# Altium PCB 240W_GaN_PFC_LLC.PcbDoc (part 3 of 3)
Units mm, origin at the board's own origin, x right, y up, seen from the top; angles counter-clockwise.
Board outline 105 x 71.8 mm, 4 copper layers (Top Layer, Layer 1, Layer 2, Bottom Layer), stack 1.787 mm thick; 165 components, 88 nets, 549 pads, 326 vias.
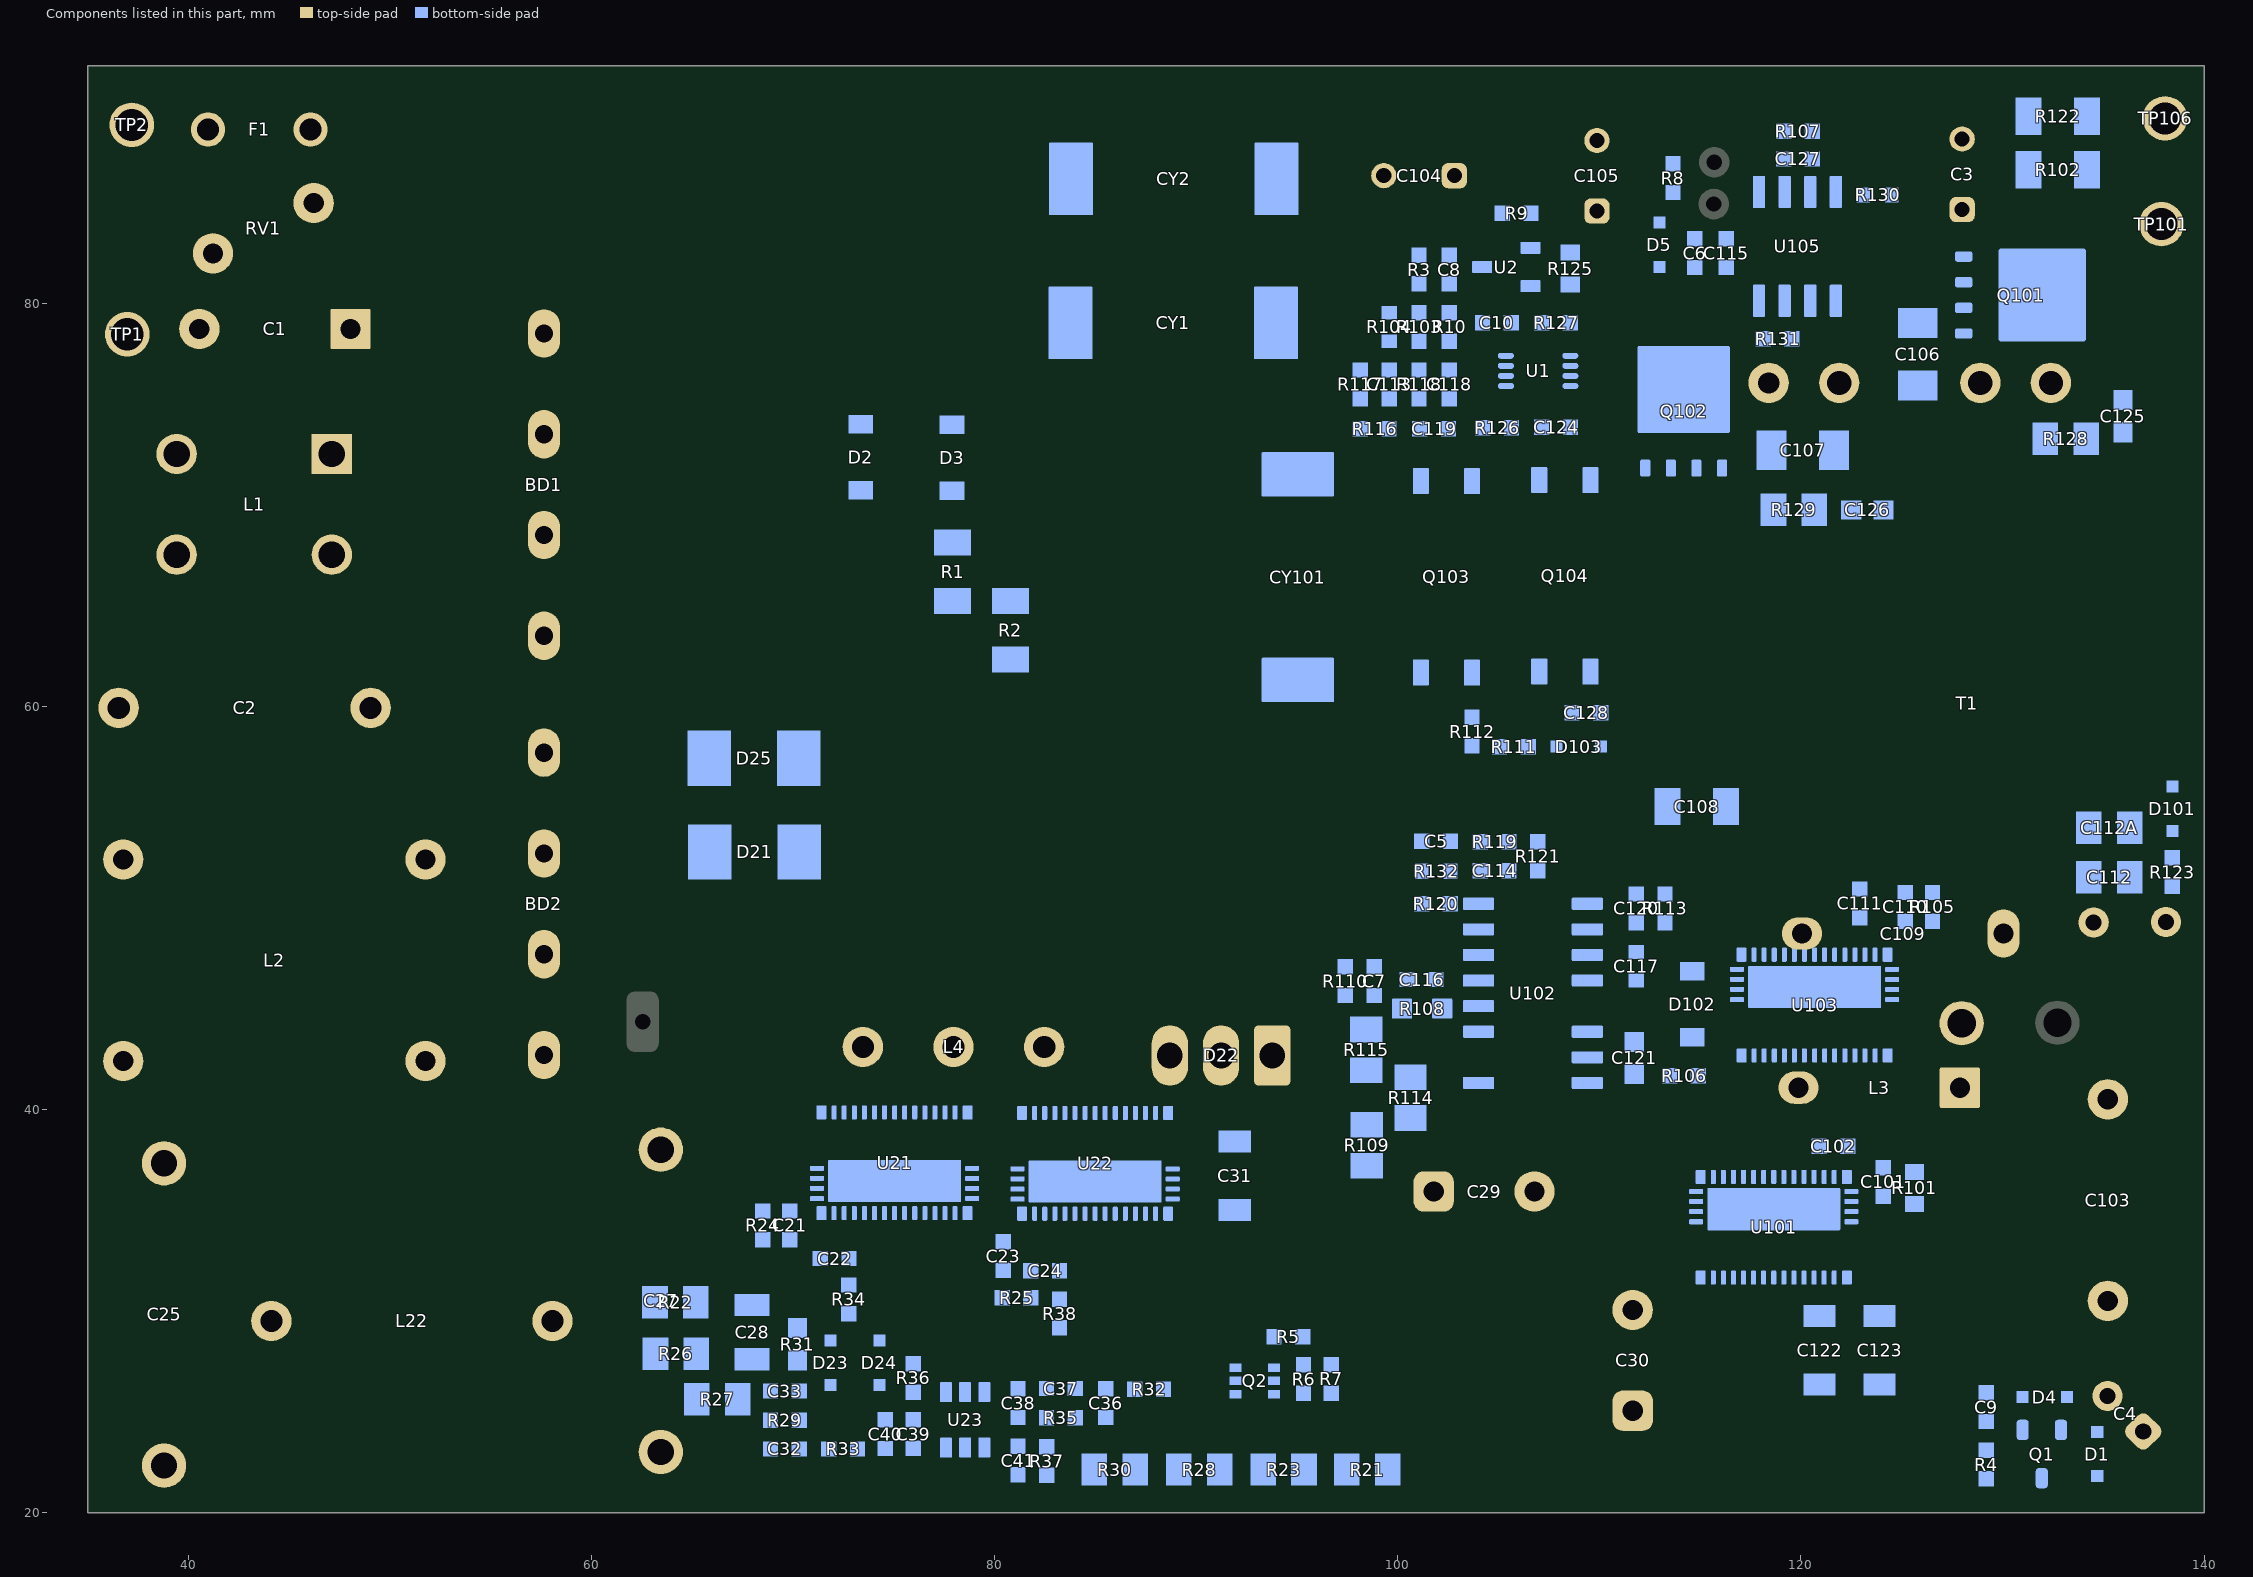
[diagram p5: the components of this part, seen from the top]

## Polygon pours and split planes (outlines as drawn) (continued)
PGND on Bottom Layer "BOTTOM_LAYER_PGND_P221" (solid, remove dead copper, pour order 221): 18 vertices, not listed, extent 115.425,45.105 124,51.95
NetC27_1 on Bottom Layer "BOTTOM_LAYER_NETC27_1_P197" (solid, remove dead copper, pour order 197): 19 vertices, not listed, extent 55.55,27.891 74.4,46
PGND on Bottom Layer "BOTTOM_LAYER_PGND_P196" (solid, remove dead copper, pour order 196): 18 vertices, not listed, extent 81.675,25.175 93.25,37.75
PGND on Bottom Layer "BOTTOM_LAYER_PGND_P195" (solid, remove dead copper, pour order 195): 18 vertices, not listed, extent 71.725,27.775 81.3,37.8
PGND on Bottom Layer "BOTTOM_LAYER_PGND_P182" (solid, remove dead copper, pour order 182): 35 vertices, not listed, extent 101.875,43.1 111.125,62.4
PGND on Bottom Layer "BOTTOM_LAYER_PGND_P181" (solid, remove dead copper, pour order 181): 122,53.175 126.1,53.175 126.9,52.375 126.9,50.4 124.75,50.4 124.6,50.55 124.175,50.55 123.825,50.2 123.575,50.2 123.2,50.575 122.55,50.575 122.55,52.25 122.575,52.275 122,52.85
SW on Bottom Layer "BOTTOM_LAYER_SW_P180" (solid, remove dead copper, pour order 180): 120.675,34.05 120.675,36.1 119.9,36.1 119.775,36.225 119.775,37.875 119.525,38.125 117.95,38.125 116.975,39.1 114.6,39.1 113.9,38.4 113.9,34.15 114.45,33.6 120.375,33.6 120.675,33.9
SW on Bottom Layer "BOTTOM_LAYER_SW_P179" (solid, remove dead copper, pour order 179): 123.7,43.6 117.7,43.6 117.575,43.475 117.575,41.9 119.325,40.15 121.95,40.15 123.15,41.35 123.15,42.05 123.525,42.425 123.8,42.7 123.8,43.5
PGND on Layer 2 "LAYER_2_PGND_P334" (solid, remove dead copper, pour order 334): 36 vertices, not listed, extent 105.475,22.925 126.897,51.406
NetC2_1 on Layer 2 "LAYER_2_NETC2_1_P302" (solid, remove dead copper, pour order 302): 17 vertices, not listed, extent 35.436,51.4 41.561,68.527
NetC2_2 on Layer 2 "LAYER_2_NETC2_2_P308" (solid, remove dead copper, pour order 308): 24 vertices, not listed, extent 35.625,41.35 50.025,68.75
NetC1_1 on Layer 2 "LAYER_2_NETC1_1_P349" (solid, remove dead copper, pour order 349): 18 vertices, not listed, extent 44.325,71.575 50.125,90.525
NetF1_2 on Layer 2 "LAYER_2_NETF1_2_P342" (solid, remove dead copper, pour order 342): 41.8,88.125 41.4,87.725 35.65,87.725 35.4,87.975 35.4,90.075 36,90.675 40.725,90.675 41.8,89.6
NetC1_2 on Layer 2 "LAYER_2_NETC1_2_P345" (solid, remove dead copper, pour order 345): 21 vertices, not listed, extent 35.401,70.629 42.175,83.65
NetL3_1 on Layer 2 "LAYER_2_NETL3_1_P340" (solid, remove dead copper, pour order 340): 126.45,40.45 126.95,39.95 128.975,39.95 129.275,40.25 129.275,44.849 128.724,45.4 127.383,45.4 126.45,44.467
NetC103_2 on Layer 2 "LAYER_2_NETC103_2_P338" (solid, remove dead copper, pour order 338): 130.992,49.925 131.473,49.443 131.473,48.75 136.651,43.572 136.651,39.374 135.951,38.674 133.076,38.674 130.9,40.85 130.9,44.8 129.225,46.475 129.225,49.45 129.7,49.925
PGND on Layer 2 "LAYER_2_PGND_P293" (solid, remove dead copper, pour order 293): 35 vertices, not listed, extent 96.975,43.075 137.1,62.4
390V_BUS on Layer 2 "LAYER_2_390V_BUS_P335" (solid, remove dead copper, pour order 335): 112.15,26.375 108.6,26.375 103.325,31.65 103.325,36.225 102.2,37.35 100.9,37.35 100.05,36.5 100.05,26.65 102.95,23.75 112.125,23.75 112.7,24.325 112.7,25.825
VFB on Layer 2 "LAYER_2_VFB_P331" (solid, remove dead copper, pour order 331): 139.313,84.813 138.73,85.395 127.645,85.395 127.25,85 127.25,82.934 128.984,81.2 138.8,81.2 139.313,81.712
RTN on Layer 2 "LAYER_2_RTN_P329" (solid, remove dead copper, pour order 329): 103.627,85.115 107.073,85.115 110.05,82.138 110.05,71.038 109.455,70.442 99.881,70.442 98.2,72.123 98.2,79.688
RTN on Layer 2 "LAYER_2_RTN_P328" (solid, remove dead copper, pour order 328): 29 vertices, not listed, extent 92.925,66.375 139.353,91.075
OCP on Layer 2 "LAYER_2_OCP_P326" (solid, remove dead copper, pour order 326): 138.8,91.075 134.051,91.075 133.525,90.549 133.525,86.129 133.559,86.129 133.962,85.725 139.025,85.725 139.325,86.025 139.325,90.55
VFB on Layer 2 "LAYER_2_VFB_P287" (solid, remove dead copper, pour order 287): 128.45,70.2 128.45,74.412 130.013,75.975 132.534,75.975 133.225,75.284 133.225,72.794 131.731,71.3 131.731,70.278 131.216,69.762 128.962,69.762
VFB on Layer 2 "LAYER_2_VFB_P283" (solid, remove dead copper, pour order 283): 128.225,70.55 128.225,72.15 131.375,75.3 136.55,75.3 137.45,74.4 137.45,70.425 136,68.975 129.7,68.975
BD+ on Layer 2 "LAYER_2_BD+_P272" (solid, remove dead copper, pour order 272): 63.821,87.075 67.04,87.075 75.79,78.325 84.025,78.325 85.575,76.775 85.575,67.308 91.002,61.881 91.043,61.881 91.043,50.22 89.273,48.45 74.449,48.45 71.062,51.837 69.456,51.837 69.094,51.475 63.846,51.475
NetBD1_2 on Layer 2 "LAYER_2_NETBD1_2_P269" (solid, remove dead copper, pour order 269): 59.25,74.175 59.25,68.175 58.1,67.025 54.6,67.025 53.25,68.375 53.25,73.65 54.6,75 58.425,75
BD+ on Layer 2 "LAYER_2_BD+_P227" (solid, remove dead copper, pour order 227): 19 vertices, not listed, extent 54.6,51.475 66.925,87.075
NetBD2_2 on Layer 2 "LAYER_2_NETBD2_2_P232" (solid, remove dead copper, pour order 232): 17 vertices, not listed, extent 50.6,41.375 59,54.075
BD+ on Layer 2 "LAYER_2_BD+_P260" (solid, remove dead copper, pour order 260): 27 vertices, not listed, extent 36.825,28.65 55.9,59.325
PGND on Layer 2 "LAYER_2_PGND_P253" (solid, remove dead copper, pour order 253): 26 vertices, not listed, extent 36.3,21.05 65.325,48.625
SW on Layer 2 "LAYER_2_SW_P214" (solid, remove dead copper, pour order 214): 120.875,42.775 120.125,43.525 115.682,43.525 114.932,44.275 108.65,44.275 108.025,43.65 108.025,40.537 108.462,40.1 112.025,40.1 113.9,38.225 113.9,34.175 114.45,33.625 120.31,33.625 120.875,34.19
PGND on Layer 2 "LAYER_2_PGND_P202" (solid, remove dead copper, pour order 202): 33 vertices, not listed, extent 71.725,25.175 93.2,38.732
NetC27_1 on Layer 2 "LAYER_2_NETC27_1_P199" (solid, remove dead copper, pour order 199): 17 vertices, not listed, extent 55.55,27.891 74.382,46
PGND on Layer 2 "LAYER_2_PGND_P191" (solid, remove dead copper, pour order 191): 50 vertices, not listed, extent 66.975,21 87.875,37.5
PGND on Layer 1 "LAYER_1_PGND_P216" (solid, remove dead copper, pour order 216): 112.025,32.05 131.075,32.05 132.9,30.225 132.9,23.375 131.95,22.425 116.857,22.425 115.682,23.6 115.682,26.768 115.36,27.09 112.025,27.09
PGND on Layer 1 "LAYER_1_PGND_P194" (solid, remove dead copper, pour order 194): 88.3,38.925 69.575,38.925 62.125,31.475 62.125,22.025 63.05,21.1 107.5,21.1 113.35,26.95 113.35,31.825 111.896,33.279 111.896,36.97 110.991,37.875 106.375,37.875 96.325,37.875 95.275,38.925
VFB on Layer 1 "LAYER_1_VFB_P358" (solid, remove dead copper, pour order 358): 32 vertices, not listed, extent 92.925,66.386 139.353,91.1
NetC2_2 on Layer 1 "LAYER_1_NETC2_2_P356" (solid, remove dead copper, pour order 356): 24 vertices, not listed, extent 35.625,41.35 50.025,68.75
NetC2_1 on Layer 1 "LAYER_1_NETC2_1_P355" (solid, remove dead copper, pour order 355): 17 vertices, not listed, extent 35.436,51.4 41.561,68.527
NetC1_1 on Layer 1 "LAYER_1_NETC1_1_P350" (solid, remove dead copper, pour order 350): 19 vertices, not listed, extent 44.325,70.625 50.125,90.525
NetF1_2 on Layer 1 "LAYER_1_NETF1_2_P346" (solid, remove dead copper, pour order 346): 41.8,88.125 41.4,87.725 35.65,87.725 35.4,87.975 35.4,90.075 36,90.675 40.725,90.675 41.8,89.6
NetC1_2 on Layer 1 "LAYER_1_NETC1_2_P347" (solid, remove dead copper, pour order 347): 21 vertices, not listed, extent 35.401,70.629 42.175,83.65
NetC103_2 on Layer 1 "LAYER_1_NETC103_2_P341" (solid, remove dead copper, pour order 341): 130.992,49.925 131.473,49.443 131.473,48.75 136.651,43.572 136.651,39.374 135.951,38.674 133.076,38.674 130.9,40.85 130.9,44.8 129.225,46.475 129.225,49.45 129.7,49.925
NetL3_1 on Layer 1 "LAYER_1_NETL3_1_P339" (solid, remove dead copper, pour order 339): 126.45,40.45 126.95,39.95 128.975,39.95 129.275,40.25 129.275,44.849 128.724,45.4 127.383,45.4 126.45,44.467
OCP on Layer 1 "LAYER_1_OCP_P325" (solid, remove dead copper, pour order 325): 138.8,91.075 134.051,91.075 133.525,90.549 133.525,86.129 133.559,86.129 133.962,85.725 139.025,85.725 139.325,86.025 139.325,90.55
VCCP on Layer 1 "LAYER_1_VCCP_P219" (solid, remove dead copper, pour order 219): 31 vertices, not listed, extent 99.775,42.55 139.566,62.339
PGND on Layer 1 "LAYER_1_PGND_P271" (solid, remove dead copper, pour order 271): 50 vertices, not listed, extent 49.15,28.653 91.966,85.525
BD+ on Layer 1 "LAYER_1_BD+_P255" (solid, remove dead copper, pour order 255): 43.95,39.2 46.65,36.5 46.65,29.775 45.15,28.275 38.875,28.275 35.825,31.325 35.825,37.975 37.05,39.2
NetBD1_2 on Layer 1 "LAYER_1_NETBD1_2_P265" (solid, remove dead copper, pour order 265): 20 vertices, not listed, extent 50.125,51.4 59.2,74.925
NetBD2_2 on Layer 1 "LAYER_1_NETBD2_2_P263" (solid, remove dead copper, pour order 263): 17 vertices, not listed, extent 50.6,41.375 59,54.075
PGND on Layer 1 "LAYER_1_PGND_P254" (solid, remove dead copper, pour order 254): 36.75,24.275 36.75,22.325 38.075,21 64.1,21 65.325,22.225 65.325,27.2 62.658,27.2 60.908,25.45 37.925,25.45
PGND on Layer 1 "LAYER_1_PGND_P222" (solid, remove dead copper, pour order 222): 121.1,46.025 121.1,45.15 122.405,43.845 122.405,32.605 121.675,31.875 121.675,30.275 122.225,29.725 127.675,29.725 127.7,29.75 127.65,29.8 127.65,31.425 124.95,34.125 124.95,44.925 123.825,46.05
PGND on Layer 1 "LAYER_1_PGND_P217" (solid, remove dead copper, pour order 217): 116.4,51.925 115.325,50.85 115.325,46.125 116.345,45.105 123.78,45.105 124,45.325 124,47.455 123.83,47.625 122.025,47.625 121.825,47.825 121.825,48.075 121.25,48.65 121.25,51.55 120.875,51.925
SW on Layer 1 "LAYER_1_SW_P213" (solid, remove dead copper, pour order 213): 120.875,42.775 120.125,43.525 115.682,43.525 114.932,44.275 110.494,44.275 109.525,43.306 109.525,40.932 110.357,40.1 112.025,40.1 113.9,38.225 113.9,34.175 114.45,33.625 120.31,33.625 120.875,34.19
NetC27_1 on Layer 1 "LAYER_1_NETC27_1_P193" (solid, remove dead copper, pour order 193): 17 vertices, not listed, extent 55.55,27.891 74.353,46
VFB on Top Layer "TOP_LAYER_VFB_P357" (solid, remove dead copper, pour order 357): 32 vertices, not listed, extent 92.925,66.386 139.353,91.1
NetC2_1 on Top Layer "TOP_LAYER_NETC2_1_P351" (solid, remove dead copper, pour order 351): 17 vertices, not listed, extent 35.436,51.4 41.561,68.527
NetC2_2 on Top Layer "TOP_LAYER_NETC2_2_P352" (solid, remove dead copper, pour order 352): 24 vertices, not listed, extent 35.625,41.35 50.025,68.75
NetC1_1 on Top Layer "TOP_LAYER_NETC1_1_P250" (solid, remove dead copper, pour order 250): 19 vertices, not listed, extent 44.325,70.625 50.125,90.525
NetC1_2 on Top Layer "TOP_LAYER_NETC1_2_P311" (solid, remove dead copper, pour order 311): 21 vertices, not listed, extent 35.401,70.629 42.175,83.65
NetF1_2 on Top Layer "TOP_LAYER_NETF1_2_P243" (solid, remove dead copper, pour order 243): 41.8,88.125 41.4,87.725 35.65,87.725 35.4,87.975 35.4,90.075 36,90.675 40.725,90.675 41.8,89.6
NetC103_2 on Top Layer "TOP_LAYER_NETC103_2_P336" (solid, remove dead copper, pour order 336): 130.992,49.925 131.473,49.443 131.473,48.75 136.651,43.572 136.651,39.374 135.951,38.674 133.076,38.674 130.9,40.85 130.9,44.8 129.225,46.475 129.225,49.45 129.7,49.925
NetL3_1 on Top Layer "TOP_LAYER_NETL3_1_P282" (solid, remove dead copper, pour order 282): 126.45,40.45 126.95,39.95 128.975,39.95 129.275,40.25 129.275,44.849 128.724,45.4 127.383,45.4 126.45,44.467
OCP on Top Layer "TOP_LAYER_OCP_P327" (solid, remove dead copper, pour order 327): 138.8,91.075 134.051,91.075 133.525,90.549 133.525,86.129 133.559,86.129 133.962,85.725 139.025,85.725 139.325,86.025 139.325,90.55
BD+ on Top Layer "TOP_LAYER_BD+_P268" (solid, remove dead copper, pour order 268): 43.963,39.212 46.663,36.512 46.663,29.787 45.163,28.287 38.888,28.287 35.838,31.338 35.838,37.987 37.063,39.212
NetBD2_2 on Top Layer "TOP_LAYER_NETBD2_2_P262" (solid, remove dead copper, pour order 262): 17 vertices, not listed, extent 50.6,41.375 59,54.075
PGND on Top Layer "TOP_LAYER_PGND_P256" (solid, remove dead copper, pour order 256): 36.75,24.275 36.75,22.325 38.075,21 64.1,21 65.325,22.225 65.325,27.2 62.658,27.2 60.908,25.45 37.925,25.45
NetC1_1 on Top Layer "TOP_LAYER_NETC1_1_P241" (solid, remove dead copper, pour order 241): 19 vertices, not listed, extent 44.15,70.625 50.125,90.525
PGND on Top Layer "TOP_LAYER_PGND_P236" (solid, remove dead copper, pour order 236): 30 vertices, not listed, extent 62.325,42.324 105.95,90.55
PGND on Top Layer "TOP_LAYER_PGND_P230" (solid, remove dead copper, pour order 230): 19 vertices, not listed, extent 56.7,41.25 64.325,65.55
NetBD1_2 on Top Layer "TOP_LAYER_NETBD1_2_P228" (solid, remove dead copper, pour order 228): 17 vertices, not listed, extent 50.125,51.4 59.2,74.925
390V_BUS on Top Layer "TOP_LAYER_390V_BUS_P226" (solid, remove dead copper, pour order 226): 22 vertices, not listed, extent 90.35,23.45 112.975,44.455
PGND on Top Layer "TOP_LAYER_PGND_P223" (solid, remove dead copper, pour order 223): 35 vertices, not listed, extent 93.65,29.025 128.025,62.525
PGND on Top Layer "TOP_LAYER_PGND_P218" (solid, remove dead copper, pour order 218): 116.65,51.9 115.775,51.025 115.775,48.7 115.325,48.25 115.325,46.125 116.345,45.105 123.78,45.105 124,45.325 124,47.175 121.675,49.5 121.675,51.35 121.125,51.9
SW on Top Layer "TOP_LAYER_SW_P215" (solid, remove dead copper, pour order 215): 120.95,42.7 120.125,43.525 115.682,43.525 114.932,44.275 110.494,44.275 109.525,43.306 109.525,40.932 110.357,40.1 112.025,40.1 113.9,38.225 113.9,34.175 114.45,33.625 120.31,33.625 120.95,34.265
390V_BUS on Top Layer "TOP_LAYER_390V_BUS_P212" (solid, remove dead copper, pour order 212): 137.3,30.9 137.3,28.7 136.45,27.85 128.5,27.85 127.6,28.75 118.5,28.75 116.95,27.2 116.95,24.225 116.175,23.45 108.675,23.45 108.675,27.125 112.625,27.125 117.6,32.1 136.1,32.1
PGND on Top Layer "TOP_LAYER_PGND_P211" (solid, remove dead copper, pour order 211): 118.575,26.6 118.575,23.55 119.625,22.5 126.825,22.5 127.425,23.1 127.425,26.375 126.625,27.175 119.15,27.175
LMG_VCC on Top Layer "TOP_LAYER_LMG_VCC_P201" (solid, remove dead copper, pour order 201): 21 vertices, not listed, extent 70.375,21.175 83.875,34.825
PGND on Top Layer "TOP_LAYER_PGND_P200" (solid, remove dead copper, pour order 200): 29 vertices, not listed, extent 62.15,21 93.25,38.925
NetC27_1 on Top Layer "TOP_LAYER_NETC27_1_P198" (solid, remove dead copper, pour order 198): 17 vertices, not listed, extent 55.55,27.891 74.4,46

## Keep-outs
Keep-Out Layer:
  the board outline again, w0.2
  text ".Layer_Name" at 14.656,-21.806 h1.52

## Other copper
Top Layer:
  pour cut-out: 123.38,52.081 ccw(c123.88,52.081) 123.88,51.581 ccw(c123.88,52.081) 124.38,52.081 ccw(c123.88,52.081) 123.88,52.581 ccw(c123.88,52.081)
  pour cut-out: 95.2,28.405 ccw(c96.7,28.405) 96.7,26.905 ccw(c96.7,28.405) 98.2,28.405 ccw(c96.7,28.405) 96.7,29.905 ccw(c96.7,28.405)
  pour cut-out: 93.772,29.75 ccw(c95.272,29.75) 95.272,28.25 ccw(c95.272,29.75) 96.772,29.75 ccw(c95.272,29.75) 95.272,31.25 ccw(c95.272,29.75)
  pour cut-out: 105.429,72.607 ccw(c105.929,72.607) 105.929,72.107 ccw(c105.929,72.607) 106.429,72.607 ccw(c105.929,72.607) 105.929,73.107 ccw(c105.929,72.607)
  pour cut-out: 77.9,78.784 cw(c77.9,80.484) 76.2,80.484 cw(c77.9,80.484) 77.9,82.184 cw(c77.9,80.484) 79.6,80.484 cw(c77.9,80.484)
  pour cut-out: 75.643,85.775 cw(c75.643,87.475) 73.943,87.475 cw(c75.643,87.475) 75.643,89.175 cw(c75.643,87.475) 77.343,87.475 cw(c75.643,87.475)
  pour cut-out: 82.475,60.748 cw(c82.475,62.348) 80.875,62.348 cw(c82.475,62.348) 82.475,63.948 cw(c82.475,62.348) 84.075,62.348 cw(c82.475,62.348)
  pour cut-out: 70.325,48.335 cw(c70.325,49.935) 68.725,49.935 cw(c70.325,49.935) 70.325,51.535 cw(c70.325,49.935) 71.925,49.935 cw(c70.325,49.935)
  pour cut-out: 112.189,48.225 ccw(c112.789,48.225) 112.789,47.625 ccw(c112.789,48.225) 113.389,48.225 ccw(c112.789,48.225) 112.789,48.825 ccw(c112.789,48.225)
  pour cut-out: 99.18,47.454 ccw(c99.78,47.454) 99.78,46.854 ccw(c99.78,47.454) 100.38,47.454 ccw(c99.78,47.454) 99.78,48.054 ccw(c99.78,47.454)
  text ".Layer_Name" at 14.656,-21.806 h1.52
Layer 1:
  pour cut-out: 81.294,29.61 ccw(c81.794,29.61) 81.794,29.11 ccw(c81.794,29.61) 82.294,29.61 ccw(c81.794,29.61) 81.794,30.11 ccw(c81.794,29.61)
  pour cut-out: 105.444,72.592 ccw(c105.944,72.592) 105.944,72.092 ccw(c105.944,72.592) 106.444,72.592 ccw(c105.944,72.592) 105.944,73.092 ccw(c105.944,72.592)
  pour cut-out: 77.9,78.784 cw(c77.9,80.484) 76.2,80.484 cw(c77.9,80.484) 77.9,82.184 cw(c77.9,80.484) 79.6,80.484 cw(c77.9,80.484)
  pour cut-out: 99.275,35.873 ccw(c101.775,35.873) 101.775,33.373 ccw(c101.775,35.873) 104.275,35.873 ccw(c101.775,35.873) 101.775,38.373 ccw(c101.775,35.873)
  pour cut-out: 109.15,25.075 ccw(c111.65,25.075) 111.65,22.575 ccw(c111.65,25.075) 114.15,25.075 ccw(c111.65,25.075) 111.65,27.575 ccw(c111.65,25.075)
  pour cut-out: 76.3,26.05 ccw(c76.9,26.05) 76.9,25.45 ccw(c76.9,26.05) 77.5,26.05 ccw(c76.9,26.05) 76.9,26.65 ccw(c76.9,26.05)
  pour cut-out: 70.7,31.55 ccw(c71.3,31.55) 71.3,30.95 ccw(c71.3,31.55) 71.9,31.55 ccw(c71.3,31.55) 71.3,32.15 ccw(c71.3,31.55)
Layer 2:
  pour cut-out: 132.625,54.165 ccw(c133.125,54.165) 133.125,53.665 ccw(c133.125,54.165) 133.625,54.165 ccw(c133.125,54.165) 133.125,54.665 ccw(c133.125,54.165)
Bottom Layer:
  text ".Layer_Name" at 14.656,-21.806 h1.52

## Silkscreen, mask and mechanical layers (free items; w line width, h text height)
Top Overlay:
  rectangle: 60.05,39.775 62.05,90.775
  rectangle: 34.975,90.8 140,91.8
  rectangle: 35,20 140,21
  text ".Layer_Name" at 14.656,-21.806 h1.52
Bottom Overlay:
  rectangle: 34.975,90.8 140,91.8
  rectangle: 34.975,20 140,21
  text "'.PRJ_Number'.PCB_Rev" at 88.25,56.7 h2.75
  text ".Layer_Name" at 14.656,-21.806 h1.52
Top Paste:
  text ".Layer_Name" at 14.656,-21.806 h1.52
Bottom Paste:
  text ".Layer_Name" at 14.656,-21.806 h1.52
Top Solder:
  text ".Layer_Name" at 14.656,-21.806 h1.52
  text ".Layer_Name" at 14.656,-21.806 h1.52
Bottom Solder:
  text ".Layer_Name" at 14.656,-21.806 h1.52
Drill Guide:
  text ".Layer_Name" at 14.656,-21.806 h1.52
M1 Board Outline:
  the board outline again, w0.2
  text ".Layer_Name" at 14.656,-21.806 h1.52
M2 Board Dimensions:
  rectangle: 0,-6.985 3.175,-3.81
  rectangle: 3.175,-10.16 12.7,-6.985
  lines w0.178: 0,-6.985 25.4,-6.985 ; 3.175,-10.16 3.175,-3.81 ; 6.35,-10.16 6.35,-3.81 ; 12.7,-10.16 12.7,-3.81 ; 19.05,-10.16 19.05,-3.81 ; 0,-10.16 25.4,-10.16 25.4,-3.81 0,-3.81 0,-10.16
  text ".Layer_Name" at 14.656,-21.806 h1.52
M3 3D STEP Top:
  text ".Layer_Name" at 14.656,-21.806 h1.52
M4 3D STEP Bottom:
  text ".Layer_Name" at 14.656,-21.806 h1.52
M5 Assembly Top:
  lines w0.254: -7.417,-23.626 160.223,-23.626 ; -7.417,-18.462 160.274,-18.462 ; -7.417,-13.297 -7.417,-28.791 94.31,-28.791 160.274,-28.791 160.274,-13.297 -7.404,-13.297 -7.404,-28.791 32.614,-28.791 ; 55.194,-28.791 55.194,-13.297 ; 87.376,-18.462 87.376,-13.297 ; 108.712,-18.462 108.712,-13.297 ; 124.511,-28.956 124.511,-23.804
  text "COMPONENTS MARKED 'DNP' SHOULD NOT BE POPULATED." at 29.299,-8.09 h1.52
  text "ASSEMBLY VARIANT:" at 29.286,-11.024 h1.52
  text ".VariantName" at 55.601,-11.024 h1.52
  text "PCB VIEWED FROM TOP SIDE" at -5.804,-16.654 h1.52
  text "BOARD #:" at 57.099,-16.654 h1.52
  text ".PRJ_Number" at 70.955,-16.654 h1.52
  text "REV:" at 92.405,-16.654 h1.52
  text ".PCB_Rev" at 99.809,-16.654 h1.52
  text "SVN REV:" at 113.69,-16.654 h1.52
  text ".VersionControl_RevNumber" at 126.543,-16.654 h1.52
  text "TID #:" at 57.099,-21.819 h1.52
  text ".TID" at 70.955,-21.819 h1.52
  text "PLOT NAME =" at -5.804,-27.034 h1.52
  text ".plot_File_Name" at 14.656,-27.034 h1.52
  text "GENERATED    :" at 57.15,-27.034 h1.52
  text ".Print_Date" at 79.235,-27.034 h1.52
  text ".Print_Time" at 97.752,-27.034 h1.52
  text "TEXAS INSTRUMENTS" at 129.87,-27.034 h1.52
M6 Assembly Bottom:
  lines w0.254: -7.429,-18.474 160.261,-18.474 ; -7.379,-23.639 160.261,-23.639 ; 28.334,-28.969 28.334,-23.817 ; 44.133,-18.474 44.133,-13.31 ; 65.468,-18.474 65.468,-13.31 ; 97.65,-28.804 97.65,-13.31 ; 120.231,-28.804 160.249,-28.804 160.249,-13.31 -7.429,-13.31 -7.429,-28.804 58.534,-28.804 160.261,-28.804 160.261,-13.31
  text "COMPONENTS MARKED 'DNP' SHOULD NOT BE POPULATED." at 154.991,-8.077 h1.52
  text ".VariantName" at 128.473,-11.024 h1.52
  text "ASSEMBLY VARIANT:" at 154.864,-11.024 h1.52
  text ".VersionControl_RevNumber" at 26.302,-16.667 h1.52
  text "SVN REV:" at 39.154,-16.667 h1.52
  text ".PCB_Rev" at 53.035,-16.667 h1.52
  text "REV:" at 60.439,-16.667 h1.52
  text ".PRJ_Number" at 81.89,-16.667 h1.52
  text "BOARD #:" at 95.745,-16.667 h1.52
  text "PCB VIEWED FROM BOTTOM SIDE" at 158.648,-16.667 h1.52
  text ".TID" at 81.89,-21.831 h1.52
  text "TID #:" at 95.745,-21.831 h1.52
  text "TEXAS INSTRUMENTS" at 22.974,-27.047 h1.52
  text ".Print_Time" at 55.093,-27.047 h1.52
  text ".Print_Date" at 73.609,-27.047 h1.52
  text "GENERATED    :" at 95.694,-27.047 h1.52
  text ".plot_File_Name" at 138.189,-27.047 h1.52
  text "PLOT NAME =" at 158.648,-27.047 h1.52
M9 Title Sheet:
  drawing of 57 lines, arcs and shapes, not listed
  text "1" at 18.792,204.127 h1.78
  text "2" at 82.182,204.127 h1.78
  text "3" at 145.411,204.127 h1.78
  text "4" at 209.08,204.127 h1.78
  text "5" at 272.555,204.127 h1.78
  text "6" at 336.182,204.127 h1.78
  text "A" at -10.579,175.095 h1.78
  text "A" at 365.341,175.095 h1.78
  text "B" at -10.579,114.643 h1.78
  text "B" at 365.341,114.643 h1.78
  text "C" at -10.579,54.318 h1.78
  text "C" at 365.341,54.318 h1.78
  text "PROJECT TITLE:" at 288.125,7.048 h1.14
  text ".PRJ_Title" at 289.395,3.662 h1.78
  text "DESIGNED FOR:" at 288.125,-0.597 h1.14
  text ".PRJ_Customer" at 289.395,-4.153 h1.78
  text "D" at -10.579,-5.88 h1.78
  text "D" at 365.341,-5.88 h1.78
  text "FILE NAME:" at 288.125,-8.217 h1.14
  text ".PCB_File_Name_No_Path" at 289.395,-11.265 h1.78
  text "Texas Instruments (TI) and/or its licensors do not warrant the accuracy or completeness of this specification" at 161.9,-15.376 h1.14
  text "ENGINEER:" at 288.125,-15.583 h1.14
  text "LAYOUT BY:" at 326.352,-15.583 h1.14
  text "or any information contained therein. TI and/or its licensors do not warrant that this design will meet" at 160.757,-18.237 h1.14
  text ".PRJ_Engineer" at 289.395,-19.52 h1.78
  text ".PCB_Layout" at 327.635,-19.52 h1.78
  text "the specifications, will be suitable for your application or fit for any particular purpose, or will operate in" at 160.757,-21.099 h1.14
  text ".Layer_Name" at 14.656,-21.806 h1.52
  text "ALTIUM DESIGNER VERSION:" at 326.352,-23.457 h1.14
  text "an implementation. TI and/or its licensors do not warrant that the design is production worthy. You should" at 160.757,-23.961 h1.14
  text "completely validate and test your design implementation to confirm the system functionality for your application." at 161.9,-26.822 h1.14
  text ".print_Scale" at 289.395,-26.843 h1.78
  text ".Application_BuildNumber" at 327.635,-26.843 h1.78
  text "1" at 18.792,-32.093 h1.78
  text "2" at 82.182,-32.093 h1.78
  text "3" at 145.411,-32.093 h1.78
  text "4" at 209.08,-32.093 h1.78
  text "5" at 272.555,-32.093 h1.78
  text "6" at 336.182,-32.093 h1.78
M10 Fab Notes:
  drawing of 189 lines, arcs and shapes, not listed
  text "DESIGN INFORMATION" at 314.503,161.447 h1.52
  text "MIN. TRACK WIDTH:" at 298.131,158.091 h1.52
  text "8" at 325.976,158.091 h1.52
  text "MIL" at 329.907,158.091 h1.52
  text "7.874" at 321.75,155 h1.52
  text "MIN. CLEARANCE:" at 298.131,154.938 h1.52
  text "MIL" at 329.907,154.938 h1.52
  text "MIN. VIA PAD SIZE:" at 298.131,151.785 h1.52
  text "24" at 325.214,151.785 h1.52
  text "MIL" at 329.907,151.785 h1.52
  text "0.05mm (2MIL)" at 315.784,148.486 h1.52
  text "MINIMUM ANNULAR RING" at 289.769,148.277 h1.52
  text "EXTERNAL" at 333.768,148.277 h1.52
  text "PER" at 294.849,145.48 h1.52
  text "IPC-D-275 CLASS 2 LEVEL C" at 300.437,145.48 h1.52
  text "MIL, HOLES" at 338.238,142.928 h1.52
  text "+/-" at 328.27,142.709 h1.52
  text "+/-" at 349.961,142.709 h1.52
  text "REGISTRATION TOLERANCES:" at 289.769,142.682 h1.52
  text "METAL" at 320.243,142.682 h1.52
  text "5" at 334.879,142.683 h1.52
  text "3" at 356.037,142.683 h1.52
  text "MIL" at 358.99,142.682 h1.52
  text "HOLE SIZE TOLERANCE (UNLESS OTHERWISE SPECIFIED):" at 289.769,140.185 h1.52
  text "+/-" at 349.961,140.112 h1.52
  text "3" at 356.037,140.085 h1.52
  text "MIL" at 358.99,140.085 h1.52
  text "MATERIAL:" at 287.87,136.589 h1.52
  text "FR-4 High Tg" at 312.926,133.324 h1.52
  text "X" at 309.257,133.122 h1.52
  text "FR-4" at 298.563,133.007 h1.52
  text "OTHER" at 336.358,133.007 h1.52
  text "62 MIL (1.6mm) +/-10%" at 306.694,129.374 h1.52
  text "X" at 303.643,129.312 h1.52
  text "THICKNESS:" at 289.769,129.165 h1.52
  text "OTHER" at 339.33,129.165 h1.52
  text "TOLERANCE:" at 289.769,125.652 h1.52
  text "X" at 311.314,125.652 h1.52
  text "ANSI IPC-6012 TYPE 3 CLASS 2" at 315.836,125.652 h1.52
  text "OTHER +/-" at 315.835,121.989 h1.52
  text "BOW & TWIST:" at 289.769,118.302 h1.52
  text "X" at 311.314,118.302 h1.52
  text "ANSI IPC-6012 TYPE 3 CLASS 2" at 315.836,118.302 h1.52
  text "OTHER +/-" at 315.835,114.576 h1.52
  text "DRILLING:" at 287.87,111.258 h1.52
  text "NC_DRILL FILES" at 332.599,108.586 h1.52
  text "REFERENCE:" at 289.769,108.486 h1.52
  text "X" at 306.463,108.484 h1.52
  text "AS SHOWN" at 310.984,108.486 h1.52
  text "X" at 329.348,108.486 h1.52
  text "OTHER" at 340.168,104.873 h1.52
  text "PTH COPPER THICKNESS:" at 289.761,104.783 h1.52
  text "X" at 318.697,104.783 h1.52
  text "20-30 um" at 321.948,104.783 h1.52
  text "BOARD FINISH:" at 287.87,101.034 h1.52
  text "SILKSCREEN:" at 291.812,98.237 h1.52
  text "X" at 316.14,98.237 h1.52
  text "TOP" at 319.112,98.237 h1.52
  text "X" at 329.094,98.237 h1.52
  text "BOTTOM" at 332.091,98.237 h1.52
  text "SILKSCREEN COLOR:" at 291.812,94.295 h1.52
  text "X" at 316.115,94.295 h1.52
  text "WHITE" at 319.112,94.295 h1.52
  text "OTHER" at 332.091,94.295 h1.52
  text "X" at 319.442,90.652 h1.52
  text "GREEN" at 322.439,90.652 h1.52
  text "OTHER" at 338.136,90.652 h1.52
  text "SOLDER RESIST COLOR:" at 291.812,90.477 h1.52
  text "X" at 319.442,86.734 h1.52
  text "MATTE" at 322.439,86.734 h1.52
  text "SEMI-GLOSS" at 338.125,86.717 h1.52
  text "IMMERSION GOLD (ENIG)" at 314.819,82.345 h1.52
  text "ENEPIG" at 348.793,82.162 h1.52
  text "SURFACE FINISH:" at 287.87,82.136 h1.52
  text "X" at 310.298,82.136 h1.52
  text "IMM. TIN/SILVER OR EQUIV" at 296.24,78.649 h1.52
  text "OTHER" at 332.599,78.549 h1.52
  text "ARRAY/PANEL:" at 287.87,74.602 h1.52
  text "CUT AND TRIM PER M1 BOARD OUTLINE" at 314.819,74.393 h1.52
  text "N.C. ROUTE" at 314.819,70.94 h1.52
  text "X" at 332.295,70.94 h1.52
  text "V. SCORE" at 336.816,70.94 h1.52
  text "CERTIFICATION:" at 287.87,67.66 h1.52
  text "MATERIALS AND WORKMANSHIP FOR ALL PCBS" at 306.285,67.66 h1.52
  text "TO MEET OR EXCEED THE REQUIREMENTS OF:" at 306.285,65.271 h1.52
  text "X" at 297.078,62.003 h1.52
  text "ANSI IPC-A-600F CLASS ->" at 300.329,62.003 h1.52
  text "X" at 342.188,62.003 h1.52
  text "2" at 344.982,62.003 h1.52
  text "1" at 336.981,61.965 h1.52
  text "3" at 353.973,61.965 h1.52
  text "X" at 317.702,58.252 h1.52
  text "RoHS" at 320.953,58.252 h1.52
  text "OTHER" at 337.321,58.252 h1.52
  text "PER ORDER" at 347.407,58.252 h1.52
  text "ALL BOARDS MUST MEET OR EXCEED UL94-V0 REQUIREMENTS." at 288.569,54.345 h1.52
  text "PCB MUST BEAR THE UL94V-0 UL REGISTERED MATERIAL ID NUMBER" at 288.569,51.397 h1.52
  text "ADDITIONAL REQUIREMENTS:" at 287.87,47.094 h1.52
  text "MICROSECTION:" at 289.769,44.373 h1.52
  text "YES" at 312.775,44.373 h1.52
  text "REQUIRED" at 334.657,40.707 h1.52
  text "BARE BOARD ELEC. TEST:" at 289.769,40.634 h1.52
  text "NONE" at 322.935,40.634 h1.52
  text "X" at 331.66,40.634 h1.52
  text "PER ORDER" at 349.693,40.634 h1.52
  text "XX MIL VIAS REQUIRE NON-CONDUCTIVE FILL AND PLANARIZE" at 294.04,35.428 h1.5
  text "XX MIL VIAS REQUIRE CONDUCTIVE FILL AND PLANARIZE" at 294.243,32.787 h1.52
  text "OUTER XX MIL TRACES REQUIRE 50 OHM SINGLE-ENDED IMPEDANCE" at 294.218,28.637 h1.47
  text "LAYER 2 & 3 (INNER LAYERS) XX MIL WIDE, XX MIL SPACE / TRACES REQUIRE 100 OHM DIFFERENTIAL IMPEDANCE" at 294.015,22.65 h1.52
  text ".Layer_Name" at 14.656,-21.806 h1.52
M11 Gerber Information:
  lines w0.254: -7.417,-23.626 160.223,-23.626 ; -7.417,-18.462 160.274,-18.462 ; -7.417,-13.297 -7.417,-28.791 94.31,-28.791 160.274,-28.791 160.274,-13.297 -7.404,-13.297 -7.404,-28.791 32.614,-28.791 ; 55.194,-28.791 55.194,-13.297 ; 87.376,-18.462 87.376,-13.297 ; 108.712,-18.462 108.712,-13.297 ; 124.511,-28.956 124.511,-23.804
  text "ALL ARTWORK VIEWED FROM TOP SIDE" at -5.804,-16.654 h1.52
  text "BOARD #:" at 57.099,-16.654 h1.52
  text ".PRJ_Number" at 70.955,-16.654 h1.52
  text "REV:" at 92.405,-16.654 h1.52
  text ".PCB_Rev" at 99.809,-16.654 h1.52
  text "SVN REV:" at 113.69,-16.654 h1.52
  text ".VersionControl_RevNumber" at 126.543,-16.654 h1.52
  text "LAYER NAME =" at -5.804,-21.806 h1.52
  text "TID #:" at 57.099,-21.819 h1.52
  text ".TID" at 70.955,-21.819 h1.52
  text "PLOT NAME =" at -5.804,-27.034 h1.52
  text ".plot_File_Name" at 14.656,-27.034 h1.52
  text "GENERATED    :" at 57.15,-27.034 h1.52
  text ".Print_Date" at 79.235,-27.034 h1.52
  text ".Print_Time" at 97.752,-27.034 h1.52
  text "TEXAS INSTRUMENTS" at 129.87,-27.034 h1.52
M12 Stackup:
  drawing of 295 lines, arcs and shapes, not listed
  text "Layer" at 249.469,200.023 h1.52
  text "Name" at 259.88,200.023 h1.52
  text "Material" at 283.496,200.023 h1.52
  text "Thickness" at 305.334,200.023 h1.52
  text "Constant" at 321.84,200.023 h1.52
  text "Board Layer Stack" at 336.314,200.023 h1.52
  text "Top Overlay" at 259.88,196.975 h1.52
  text "Top Solder" at 259.88,193.927 h1.52
  text "Solder Resist" at 283.496,193.927 h1.52
  text "0.40mil" at 305.334,193.927 h1.52
  text "3.5" at 321.84,193.927 h1.52
  text "1" at 249.469,190.879 h1.52
  text "Top Layer" at 259.88,190.879 h1.52
  text "1.40mil" at 305.334,190.879 h1.52
  text "Dielectric 1" at 259.88,187.831 h1.52
  text "PP-006" at 283.496,187.831 h1.52
  text "2.80mil" at 305.334,187.831 h1.52
  text "4.1" at 321.84,187.831 h1.52
  text "2" at 249.469,184.783 h1.52
  text "Layer 1" at 259.88,184.783 h1.52
  text "CF-004" at 283.496,184.783 h1.52
  text "1.38mil" at 305.334,184.783 h1.52
  text "Dielectric1" at 259.88,181.735 h1.52
  text "FR-4 High Tg" at 283.496,181.735 h1.52
  text "59.20mil" at 305.334,181.735 h1.52
  text "4.8" at 321.84,181.735 h1.52
  text "3" at 249.469,178.687 h1.52
  text "Layer 2" at 259.88,178.687 h1.52
  text "CF-004" at 283.496,178.687 h1.52
  text "1.38mil" at 305.334,178.687 h1.52
  text "Dielectric 2" at 259.88,175.639 h1.52
  text "PP-006" at 283.496,175.639 h1.52
  text "2.80mil" at 305.334,175.639 h1.52
  text "4.1" at 321.84,175.639 h1.52
  text "4" at 249.469,172.591 h1.52
  text "Bottom Layer" at 259.88,172.591 h1.52
  text "1.40mil" at 305.334,172.591 h1.52
  text "Bottom Solder" at 259.88,169.543 h1.52
  text "Solder Resist" at 283.496,169.543 h1.52
  text "0.40mil" at 305.334,169.543 h1.52
  text "3.5" at 321.84,169.543 h1.52
  text "Bottom Overlay" at 259.88,166.495 h1.52
  text ".Layer_Name" at 14.656,-21.806 h1.52
M13 Component Bodies Top:
  text ".Layer_Name" at 14.656,-21.806 h1.52
M14 Component Bodies Bottom:
  text ".Layer_Name" at 14.656,-21.806 h1.52
M15 Courtyards Top:
  lines w0.25: 124.055,79.775 124.475,79.775
  lines w1.5: 81.435,57.677 83.209,59.452 86.593,59.452 96.67,49.374 96.67,42.878 100.359,39.189 104.466,39.189 104.921,38.735 104.921,32.504 109.375,28.05 112.675,28.05 ; 89.5,39.8 89.5,38.182 93.95,33.732 93.95,26.05 ; 92.335,58.743 99.136,51.942 99.136,44.091 101.52,41.707 104.356,41.707 105.006,41.057 105.006,39.848 ; 95.551,22.651 113.026,22.651 113.957,23.582 113.957,25.693 ; 112.365,28.238 113.525,29.397 113.525,31.375 ; 114.118,45.137 110.143,45.137 108.768,43.762 108.768,40.513 109.796,39.485 111.503,39.485 112.999,37.989 112.999,33.94 114.064,32.875 124.9,32.875 ; 117.725,23.025 117.725,26.835 118.815,27.925 127.229,27.925 130.347,24.808 136.606,24.808 138.109,26.311 138.109,30.544
  lines w2: 39.1,26.9 59.85,26.9 ; 42.825,69.525 43.155,69.855 48.13,69.855 49.275,71 49.275,76.484 50.928,78.137 ; 45.375,67.075 45.405,67.045 49.545,67.045 52.128,69.628 52.128,74.623 54.841,77.336 54.841,79.071 ; 52.625,50.25 54.8,52.425 54.8,53.95 55.664,54.814 55.664,64.972 56.751,66.058 ; 54.025,39.7 54.025,41.086 55.701,42.762 55.701,43.976 57,45.275 59.033,45.275 60.028,46.27 60.028,50.5 ; 54.325,40.15 60.275,40.15 60.95,40.825 62.954,40.825 65,42.871
  lines w3.5: 35.032,85.525 41.775,85.525 43.588,87.338 43.588,89.801
  text ".Layer_Name" at 14.656,-21.806 h1.52
M16 Courtyards Bottom:
  lines w1: 125.533,40.222 125.533,44.696 ; 128.783,46.043 129.825,45.001 129.825,40.425
  lines w1.5: 59.625,40.775 62.7,40.775 65.1,43.175 65.1,44.892 67.293,47.084 85.47,47.084 ; 61.358,26.911 61.358,31.635 62.025,32.303 62.026,32.303 64.55,34.826 64.55,36.585 69.255,41.29 73.596,41.29 73.888,41.582 77.527,41.582 ; 69.72,32.262 67.742,32.262 67.1,32.904 67.1,36.275 69.372,38.547 87.778,38.547 ; 87.031,26.11 89.129,24.012 97.695,24.012 98.15,24.466 98.15,28.601 95.915,30.835 94.62,30.835 ; 89.725,40.725 89.725,37.075 90.183,36.617 93.145,36.617 94.16,35.602 94.16,25.066 ; 90.703,44.975 91.95,44.975 ; 92.948,40.375 96.091,40.375 96.915,39.552 96.915,38.701 ; 102.461,39.77 102.461,41.897 102.932,42.368 105.094,42.368 105.615,41.847 ; 107.061,40.345 107.277,40.562 107.277,43.949 108.562,45.234 ; 109.705,45.105 115.27,45.105 116.044,44.331 116.628,44.331 ; 113.444,33.075 113.691,32.828 136.434,32.828 137.672,31.59 137.672,25.572 ; 116.914,44.344 124.917,44.344 ; 117.543,22.667 117.543,27.177 118.435,28.069 133.533,28.069 133.782,27.82 136.96,27.82 ; 121.452,33.306 121.452,42.131 ; 125.533,40.222 127.405,38.35 128.202,38.35 128.971,37.581 128.971,30.765 ; 125.533,44.696 127.492,46.656 127.492,46.919 ; 125.921,31.19 125.921,38.006 ; 128.229,49.339 128.229,52.264 126.518,53.975 111.267,53.975 110.919,54.323 110.919,56.314 111.423,56.817 127.802,56.817 131.077,53.542 131.077,53.265 ; 131.67,52.754 132.228,52.196 132.228,49.265 135.38,46.114 135.62,46.114 ; 104.987,33.369 109.01,29.346 109.01,29.333 110.267,28.075 112.204,28.075 113.444,29.315 113.444,31.318 109.705,35.057 109.705,36.718 108.548,37.875 104.987,37.875 104.987,33.369
  lines w2: 35.375,50.625 38.654,50.625 41.181,53.152 41.181,57.719 39.825,59.075 ; 36.386,40.244 40.069,40.244 45.073,45.248 45.073,53.385 45.964,54.276 ; 38.025,27.175 45.625,27.175 47.825,29.375 47.825,34.95 ; 43.25,72.625 43.25,82.425 ; 46.706,57.645 49.686,57.645 51.092,59.051 51.092,66.613 49.194,68.512 49.194,73.869 49.3,73.975 ; 49.45,46.725 49.45,52.5 51.4,54.45 53.725,54.45 ; 49.775,40.375 53.525,40.375 55.325,42.175 55.325,43.625 56.975,45.275 58.899,45.275 60.022,46.398 60.022,54.069 58.982,55.109 ; 51.35,78.1 51.35,89.85 ; 52.275,50.1 52.468,50.1 54.838,52.47 54.838,56.013 55,56.175 ; 54.225,25.525 54.225,34.475 59.175,39.425 ; 55.65,76.05 55.65,60.665 58.94,60.665 60.225,61.95 60.225,74.563 58.808,75.979 56.654,75.979 ; 71.225,89 71.225,66.475 77.625,60.075 84.15,60.075
  lines w6.5: 89.304,87.63 89.304,69.471 92.322,66.452 112.574,66.452 116.527,62.499 137.331,62.499
  text ".Layer_Name" at 14.656,-21.806 h1.52
Drill Drawing:
  circle w0.254: c170.011,296.451 r0.422
  circle w0.254: c170.011,296.451 r0.703
  circle w0.254: c170.011,277.477 r0.703
  lines w0.254: 169.309,254.638 170.714,254.638 170.714,256.044 169.309,256.044 169.309,254.638 ; 169.309,259.206 170.714,259.206 170.011,257.8 169.309,259.206 ; 169.309,261.314 169.66,261.314 170.011,260.963 170.363,261.314 170.714,261.314 170.363,261.665 170.714,262.017 170.363,262.017 170.011,262.368 169.66,262.017 169.309,262.017 169.66,261.665 169.309,261.314 ; 169.309,264.125 170.714,264.125 170.714,265.531 169.309,265.531 169.309,264.125 ; 169.309,270.801 169.66,270.801 169.66,270.45 170.363,270.45 170.363,270.801 170.714,270.801 170.714,271.504 170.363,271.504 170.363,271.855 169.66,271.855 169.66,271.504 169.309,271.504 169.309,270.801 ; 169.309,275.017 170.714,275.017 170.011,273.612 169.309,275.017 ; 169.309,279.937 169.309,280.288 169.66,280.639 169.309,280.991 169.309,281.342 169.66,281.342 170.011,280.991 170.363,281.342 170.714,281.342 170.714,280.991 170.363,280.639 170.714,280.288 170.714,279.937 170.363,279.937 170.011,280.288 169.66,279.937 169.309,279.937 ; 169.309,283.45 169.66,283.45 170.011,283.099 170.363,283.45 170.714,283.45 170.363,283.802 170.714,284.153 170.363,284.153 170.011,284.504 169.66,284.153 169.309,284.153 169.66,283.802 169.309,283.45 ; 169.309,286.261 169.309,286.613 169.66,286.964 169.309,287.315 169.309,287.667 169.66,287.667 170.011,287.315 170.363,287.667 170.714,287.667 170.714,287.315 170.363,286.964 170.714,286.613 170.714,286.261 170.363,286.261 170.011,286.613 169.66,286.261 169.309,286.261 ; 169.309,289.423 170.011,289.775 170.714,289.423 170.363,290.126 170.714,290.829 170.011,290.478 169.309,290.829 169.66,290.126 169.309,289.423 ; 169.309,293.288 170.011,292.586 170.714,293.288 170.011,293.991 169.309,293.288 ; 169.59,258.925 170.433,258.925 170.011,258.082 169.59,258.925 ; 169.59,261.455 169.801,261.455 170.011,261.244 170.222,261.455 170.433,261.455 170.222,261.665 170.433,261.876 170.222,261.876 170.011,262.087 169.801,261.876 169.59,261.876 169.801,261.665 169.59,261.455 ; 169.59,264.406 170.433,264.406 170.433,265.249 169.59,265.249 169.59,264.406 ; 169.59,280.218 169.59,280.428 169.801,280.639 169.59,280.85 169.59,281.061 169.801,281.061 170.011,280.85 170.222,281.061 170.433,281.061 170.433,280.85 170.222,280.639 170.433,280.428 170.433,280.218 170.222,280.218 170.011,280.428 169.801,280.218 169.59,280.218
  lines w0.305: 168.035,253.689 250.132,253.689 ; 168.035,301.124 250.132,301.124 ; 176.62,250.527 176.62,304.286 ; 185.057,250.527 185.057,304.286 ; 201.224,250.527 201.224,304.286 ; 207.807,250.527 207.807,304.286 ; 217.338,250.527 217.338,304.286 ; 235.742,250.527 235.742,304.286 ; 168.035,250.527 250.132,250.527 250.132,304.286 168.035,304.286 168.035,250.527
  text "Symbol" at 169.932,302.073 h1.83
  text "Quantity" at 177.569,302.073 h1.83
  text "Finished Hole Size" at 186.006,302.073 h1.83
  text "Plated" at 202.172,302.073 h1.83
  text "Hole Type" at 208.756,302.073 h1.83
  text "Drill Layer Pair" at 218.287,302.073 h1.83
  text "Hole Tolerance" at 236.691,302.073 h1.83
  text "1" at 177.569,298.91 h1.52
  text "7.87mil (0.200mm)" at 186.006,298.91 h1.52
  text "PTH" at 202.172,298.91 h1.52
  text "Round" at 208.756,298.91 h1.52
  text "Top Layer - Bottom Layer" at 218.287,298.91 h1.52
  text "D" at 169.289,298.657 h1.41
  text "325" at 177.569,295.748 h1.52
  text "11.81mil (0.300mm)" at 186.006,295.748 h1.52
  text "PTH" at 202.172,295.748 h1.52
  text "Round" at 208.756,295.748 h1.52
  text "Top Layer - Bottom Layer" at 218.287,295.748 h1.52
  text "6" at 177.569,292.586 h1.52
  text "29.53mil (0.750mm)" at 186.006,292.586 h1.52
  text "PTH" at 202.172,292.586 h1.52
  text "Round" at 208.756,292.586 h1.52
  text "Top Layer - Bottom Layer" at 218.287,292.586 h1.52
  text "2" at 177.569,289.423 h1.52
  text "30.00mil (0.762mm)" at 186.006,289.423 h1.52
  text "PTH" at 202.172,289.423 h1.52
  text "Round" at 208.756,289.423 h1.52
  text "Top Layer - Bottom Layer" at 218.287,289.423 h1.52
  text "4" at 177.569,286.261 h1.52
  text "31.50mil (0.800mm)" at 186.006,286.261 h1.52
  text "PTH" at 202.172,286.261 h1.52
  text "Round" at 208.756,286.261 h1.52
  text "Top Layer - Bottom Layer" at 218.287,286.261 h1.52
  text "18" at 177.569,283.099 h1.52
  text "39.37mil (1.000mm)" at 186.006,283.099 h1.52
  text "PTH" at 202.172,283.099 h1.52
  text "Round" at 208.756,283.099 h1.52
  text "Top Layer - Bottom Layer" at 218.287,283.099 h1.52
  text "1" at 177.569,279.937 h1.52
  text "41.34mil (1.050mm)" at 186.006,279.937 h1.52
  text "PTH" at 202.172,279.937 h1.52
  text "Round" at 208.756,279.937 h1.52
  text "Top Layer - Bottom Layer" at 218.287,279.937 h1.52
  text "9" at 177.569,276.774 h1.52
  text "43.31mil (1.100mm)" at 186.006,276.774 h1.52
  text "PTH" at 202.172,276.774 h1.52
  text "Round" at 208.756,276.774 h1.52
  text "Top Layer - Bottom Layer" at 218.287,276.774 h1.52
  text "3" at 177.569,273.612 h1.52
  text "47.24mil (1.200mm)" at 186.006,273.612 h1.52
  text "PTH" at 202.172,273.612 h1.52
  text "Round" at 208.756,273.612 h1.52
  text "Top Layer - Bottom Layer" at 218.287,273.612 h1.52
  text "3" at 177.569,270.45 h1.52
  text "50.00mil (1.270mm)" at 186.006,270.45 h1.52
  text "PTH" at 202.172,270.45 h1.52
  text "Round" at 208.756,270.45 h1.52
  text "Top Layer - Bottom Layer" at 218.287,270.45 h1.52
  text "8" at 177.569,267.287 h1.52
  text "51.18mil (1.300mm)" at 186.006,267.287 h1.52
  text "PTH" at 202.172,267.287 h1.52
  text "Round" at 208.756,267.287 h1.52
  text "Top Layer - Bottom Layer" at 218.287,267.287 h1.52
  text "C" at 169.289,267.034 h1.41
  text "2" at 177.569,264.125 h1.52
  text "55.12mil (1.400mm)" at 186.006,264.125 h1.52
  text "PTH" at 202.172,264.125 h1.52
  text "Round" at 208.756,264.125 h1.52
  text "Top Layer - Bottom Layer" at 218.287,264.125 h1.52
  text "4" at 177.569,260.963 h1.52
  text "63.00mil (1.600mm)" at 186.006,260.963 h1.52
  text "PTH" at 202.172,260.963 h1.52
  text "Round" at 208.756,260.963 h1.52
  text "Top Layer - Bottom Layer" at 218.287,260.963 h1.52
  text "1" at 177.569,257.8 h1.52
  text "30.00mil (0.762mm)" at 186.006,257.8 h1.52
  text "PTH" at 202.172,257.8 h1.52
  text "Slot" at 208.756,257.8 h1.52
  text "Top Layer - Bottom Layer" at 218.287,257.8 h1.52
  text "8" at 177.569,254.638 h1.52
  text "35.43mil (0.900mm)" at 186.006,254.638 h1.52
  text "PTH" at 202.172,254.638 h1.52
  text "Slot" at 208.756,254.638 h1.52
  text "Top Layer - Bottom Layer" at 218.287,254.638 h1.52
  text "395 Total" at 177.569,251.476 h1.52
  text "Slot definitions :" at 169.932,249.262 h1.52
  text "Routed Path Length" at 181.379,249.262 h1.52
  text "= Calculated from tool start centre position to tool end centre position." at 195.091,249.262 h1.52
  text "Hole Length" at 181.379,247.997 h1.52
  text "= Routed Path Length + Tool Size = Slot length as defined in the PCB layout" at 190.015,247.997 h1.52
  text ".Layer_Name" at 14.656,-21.806 h1.52
M17 Embedded Cavity:
  text ".Layer_Name" at 14.656,-21.806 h1.52
M18 Embedded Assembly:
  text ".Layer_Name" at 14.656,-21.806 h1.52
M19 Embedded Keepout:
  text ".Layer_Name" at 14.656,-21.806 h1.52

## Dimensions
35,91.8 to 140,91.8 on M2 Board Dimensions
0,-10.16 to 25.4,-10.16 on M2 Board Dimensions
